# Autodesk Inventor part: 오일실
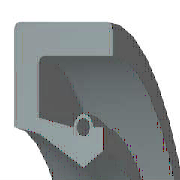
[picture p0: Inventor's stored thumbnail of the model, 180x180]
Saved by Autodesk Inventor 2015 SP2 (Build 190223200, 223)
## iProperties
IsCustomPart: 0
Created: 2009-02
Part Number: 오일실
Material: 고무
Description: 오일-실
Document SubType Name: Modeling
Standard: KS B 2804
Designer: 한국산업디자인학원 [http://gmhk.co.kr]
Standards Organization: KS
Language: ko-KR
Size Designation: S - 17 30 8
Categories: <MemberInstance><Categories><Category DisplayName="샤프트 부품" InternalName="7f7aeb1f-a693-4053-b835-cee3144e0d98" Mnemonic="SHFT"><Category DisplayName="실링" Intern
Density: 0.93 g/cm^3
Appearance: 고무 - 검은색 - 버전 1.1
Author: pww
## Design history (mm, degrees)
revolve "본체" stored, may be unused: angle "d17" = 90 deg
revolve "스프링1" stored, may be unused: angle "d18" = 90 deg
body "Solid1"
sketch "스케치1"
  geometry: L1 (0, 15)-(8, 15); L2 (8, 15)-(8, 13.75); L3 (8, 13.75)-(1.75, 13.75); L4 (0, 15)-(0, 10.6); L5 (0, 10.6)-(1.75, 10.25); L6 (1.75, 10.25)-(4.9, 8.5); L7 (4.9, 8.5)-(0, 8.5); L8 (6.3, 9.375)-(6.3, 10.6); L9 (0, 0)-(9.586, 0) reference; L10 (4.9, 8.5)-(6.3, 9.375); L11 (0, 18)-(0, -3) reference; L12 (-1.917, 0)-(11.503, 0) reference; L13 (4.2, 10.6)-(1.75, 11.09); L14 (1.75, 11.09)-(1.75, 13.75); L15 (6.3, 10.6)-(5.6, 10.6); C1 r 0.455 at (4.9, 10.6); A1 r 0.7 centre (4.9, 10.6) between (5.6, 10.6) and (4.2, 10.6)
  constraints: 26 end point, 5 horizontal alignment, 4 perpendicular, 2 centre point, 2 collinear, 2 horizontal, 2 parallel, 2 point on circle, 2 point on line, 2 vertical alignment, 1 coincident
  dimensions: "d0" = 30 diameter of L1 L9 (= SD2); "d1" = 18.75 diameter of L8.start L9 (= ABDM); "d2" = 1.25 distance of L1.end L2.end (computed from SD); "d3" = 0.91 diameter of C1 (= SPDI); "d4" = 1.4 diameter of A1 (= SPDA); "d5" = 17 diameter of L6.end L9 (= NND); "d6" = 20.5 diameter of L5.end L9 (= TKDM); "d7" = 21.2 diameter of L4.end L9 (= HLDM); "d8" = 4.9 distance from line of C1.centre L4 (= SPDST); "d9" = 6.3 distance between parallel lines of L8 L4 (= SDI); "d10" = 8 distance between parallel lines of L2 L4 (= SWDT); "d12" = 1.75 distance between parallel lines of L14 L4 (= SD)
fillet "모깎기1" dims "d11" = 0.3 (= RR)
other parameters: "SD2" = 30 [user parameter; used in 1 equation term], "SWDT" = 8 [user parameter; used in 1 equation term], "RR" = 0.3 [user parameter; used in 1 equation term], "SD" = 1.75 [user parameter; used in 2 equation terms], "NND" = 17 [user parameter; used in 1 equation term], "SPDA" = 1.4 [user parameter; used in 1 equation term], "SPDI" = 0.91 [user parameter; used in 1 equation term], "TKDM" = 20.5 [user parameter; used in 1 equation term], "HLDM" = 21.2 [user parameter; used in 1 equation term], "ABDM" = 18.75 [user parameter; used in 1 equation term], "SDI" = 6.3 [user parameter; used in 1 equation term], "SPDST" = 4.9 [user parameter; used in 1 equation term], "d13" = 0, "d14" = 0, "d15" = 0, "LAB" = 0.35 [user parameter]
